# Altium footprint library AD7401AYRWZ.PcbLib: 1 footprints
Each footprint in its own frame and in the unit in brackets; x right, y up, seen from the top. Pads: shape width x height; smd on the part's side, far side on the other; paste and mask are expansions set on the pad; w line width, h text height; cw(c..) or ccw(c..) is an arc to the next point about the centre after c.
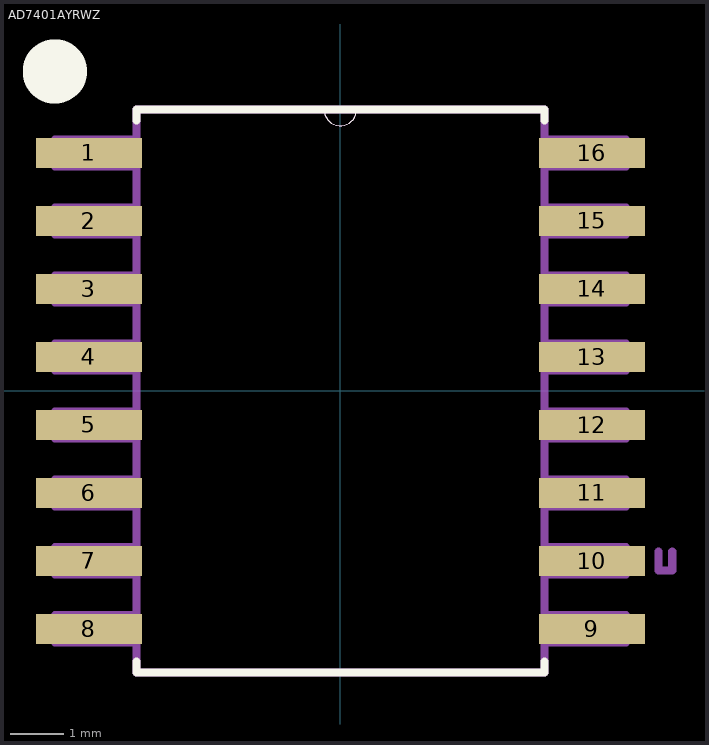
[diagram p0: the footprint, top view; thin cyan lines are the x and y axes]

## AD7401AYRWZ [mil]
pads (16):
  rect 78x22 smd: 1(-185,175) 2(-185,125) 3(-185,75) 4(-185,25) 5(-185,-25) 6(-185,-75) 7(-185,-125) 8(-185,-175) 9(185,-175) 10(185,-125) 11(185,-75) 12(185,-25) 13(185,25) 14(185,75) 15(185,125) 16(185,175)
Top Overlay:
  circle w39.37: c-210,235 r3.94
  lines w0: -12,207 ccw(c0,207) 12,207
  lines w6: -150,-199 -150,-207 150,-207 150,-199 ; -150,199 -150,207 -12,207 12,207 150,207 150,199
Mechanical 13:
  lines w0: -12,207 ccw(c0,207) 12,207
  lines w6: 234,-118 234,-132 244,-132 244,-118 ; -210,-185 -210,-165 -150,-165 -150,-185 -210,-185 ; -210,-135 -210,-115 -150,-115 -150,-135 -210,-135 ; -210,-85 -210,-65 -150,-65 -150,-85 -210,-85 ; -210,-35 -210,-15 -150,-15 -150,-35 -210,-35 ; -210,15 -210,35 -150,35 -150,15 -210,15 ; -210,65 -210,85 -150,85 -150,65 -210,65 ; -210,115 -210,135 -150,135 -150,115 -210,115 ; -210,165 -210,185 -150,185 -150,165 -210,165 ; -150,-207 150,-207 150,207 12,207 -12,207 -150,207 -150,-207 ; 150,-185 150,-165 210,-165 210,-185 150,-185 ; 150,-135 150,-115 210,-115 210,-135 150,-135 ; 150,-85 150,-65 210,-65 210,-85 150,-85 ; 150,-35 150,-15 210,-15 210,-35 150,-35 ; 150,15 150,35 210,35 210,15 150,15 ; 150,65 150,85 210,85 210,65 150,65 ; 150,115 150,135 210,135 210,115 150,115 ; 150,165 150,185 210,185 210,165 150,165
3D body "AD7401AYRWZ.STEP": height 104.33, standoff 0, extent -203.68,-202.57 202.82,202.94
